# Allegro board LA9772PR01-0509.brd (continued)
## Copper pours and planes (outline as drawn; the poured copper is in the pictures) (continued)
+PCH_VCCCLK on BOTTOM (solid shape): 34.45,120.56 34.45,117.64 34.39,117.49 34.35,117.33 34.37,117.1 34.44,116.89 34.45,116.88 34.45,116.75 34.95,116.25 34.95,115.09 34.74,114.88 33.9,114.88 33.82,114.97 33.82,115.48 33.05,116.24 33.05,119.29 33.69,119.92 33.69,120.1 33.71,120.13 33.71,120.58 33.94,120.81 33.99,120.81 34.2,120.81
+PCH_VCCCLK on BOTTOM (solid shape): 35.34,104.18 35.34,102.14 35.21,102.02 34.96,102.02 34.83,101.89 34.83,101.26 34.71,101.13 34.2,101.13 33.94,101.38 33.94,101.89 33.95,102.53 33.44,102.14 33.42,102.05 33.34,102.02 33.05,102.02 32.82,102.25 32.8,102.33 32.8,103.16 33.05,103.41 33.31,103.41 33.56,103.67 33.56,104.3 33.69,104.43 34.32,104.43 34.45,104.56 34.96,104.56
+PCH_VCCCLK on IN2 (solid shape): outline of 1015 points within 30.64,101.89 36.36,119.16
+PCH_VCCCLK3_3 on TOP (solid shape): 28.65,102.2 28.95,102.05 29.25,102.2 29.33,102.16 29.44,102.08 29.57,102.06 29.79,102.06 29.88,101.97 29.88,101.8 29.88,101.76 29.88,101.03 29.88,100.99 29.88,100.95 29.88,100.49 29.63,100.24 28.86,100.24 28.61,100.49 28.61,100.5 28.61,101.24 28.61,101.25 28.6,101.48 28.42,101.63 28.4,101.63 28.36,101.68 28.36,102.02 28.4,102.06 28.41,102.06 28.5,102.1 28.57,102.16
+PCH_VCCCLK3_3 on BOTTOM (solid shape): 17.99,107.43 17.99,106.84 18.47,106.36 18.73,106.36 19.62,105.47 19.69,105.47 19.72,105.45 19.72,104.68 19.47,104.43 19.21,104.43 18.96,104.68 18.45,104.68 18.2,104.94 18.2,105.32 17.94,105.57 17.43,105.57 17.15,105.86 17.15,107.6 17.19,107.63 17.79,107.63
+PCH_VCCCLK3_3 on IN3 (solid shape): outline of 752 points within 18.7,100.24 31.4,105.95
+PWR_SRC on TOP (solid shape): 34.58,68.96 34.58,65.95 34.46,65.83 30.77,65.83 30.51,66.08 30.51,68.95 30.9,69.33 34.21,69.33
+PWR_SRC on TOP (solid shape): 160.31,99.35 160.31,93.51 160.05,93.25 155.86,93.25 155.61,93.51 155.61,100.49 155.86,100.75 158.91,100.75
+PWR_SRC on TOP (solid shape): 184.44,64.43 184.44,61.89 184.18,61.63 175.8,61.63 175.55,61.89 175.55,64.43 175.8,64.68 184.18,64.68
+PWR_SRC on BOTTOM (solid shape): 16.98,141.05 16.98,138.94 16.86,138.82 15.29,138.82 15.16,138.95 15.16,140.96 15.3,141.1 16.94,141.1
+PWR_SRC on BOTTOM (solid shape): 184.44,24.42 184.44,21.88 184.18,21.63 178.22,21.63 177.96,21.88 177.96,24.42 178.22,24.67 184.18,24.67
+PWR_SRC on BOTTOM (solid shape): 249.34,42.84 249.34,39.03 249.08,38.77 244.64,38.77 244.38,39.03 244.38,42.84 244.64,43.09 249.08,43.09
+PWR_SRC on BOTTOM (solid shape): 158.75,102.12 158.75,101.45 158.69,100.3 158.69,99.03 158.43,98.78 155.89,98.78 155.51,99.16 155.51,101.89 155.95,102.32 158.55,102.32
+PWR_SRC on BOTTOM (solid shape): 56.38,158.58 56.38,155.39 56.09,155.1 54.87,155.1 54.71,155.27 54.71,156.69 53.95,157.45 53.95,159.25 54.09,159.39 55.57,159.39
+PWR_SRC on BOTTOM (solid shape): 80.55,9.94 80.55,4.86 80.3,4.61 75.9,4.61 75.81,4.61 74.58,4.61 74.33,4.86 74.33,6.26 78.14,10.07 80.43,10.07
+PWR_SRC on BOTTOM (solid shape): 226.6,53.12 226.6,49.69 226.48,49.57 222.67,49.57 222.28,49.19 222.28,46.39 222.03,46.14 218.47,46.14 218.22,46.39 218.22,51.64 218.69,52.11 221.27,52.11 222.54,53.38 226.35,53.38
+PWR_SRC on BOTTOM (solid shape): 190.53,43.47 190.53,40.29 190.31,40.06 186.2,40.06 185.91,39.78 185.91,38.17 185.66,37.91 182.35,37.91 181.96,37.52 181.96,33.78 181.48,33.31 176.56,33.31 176.31,33.56 176.31,39.03 176.69,39.41 179.61,39.41 183.93,43.72 190.28,43.72
+PWR_SRC on BOTTOM (solid shape): 36.24,68.56 36.24,65.95 36.15,65.85 30.36,65.85 30.26,65.95 30.26,67.87 30.6,68.21 31.61,68.21 32.02,68.62 32.02,69.19 32.04,69.21 33.55,69.21 33.77,69.43 33.77,69.75 33.53,69.99 32.08,69.99 32.03,70.03 32.03,70.64 32.18,70.79 34.02,70.79
+PWR_SRC on BOTTOM (solid shape): 176.39,64.12 176.39,63.59 176.41,63.56 177.12,63.56 177.17,63.61 177.17,64.09 177.2,64.12 177.55,64.12 177.61,64.07 177.61,63.61 177.63,63.59 178.34,63.59 178.37,63.61 178.37,64.12 178.39,64.15 179.03,64.15 179.31,63.87 179.31,62.32 179.15,62.16 175.65,62.16 175.42,62.39 175.42,63.79 175.78,64.15 176.36,64.15
+PWR_SRC on BOTTOM (solid shape): outline of 81 points within 173.11,135.64 176.69,140.9
+PWR_SRC on IN1 (solid shape): 149.89,174.28 149.89,172.25 149.64,171.99 144.31,171.99 144.05,172.25 144.05,174.28 144.31,174.53 149.64,174.53
+PWR_SRC on IN1 (solid shape): 177.83,141.39 177.83,138.85 177.1,138.11 175.45,138.11 174.71,138.86 174.71,140.11 175.71,141.12 176.3,141.12 176.82,141.64 177.58,141.64
+PWR_SRC on IN2 (solid shape): 35.09,68.24 35.09,65.87 35.03,65.81 29.3,65.81 28.99,66.12 28.99,68.11 29.37,68.49 34.83,68.49
+PWR_SRC on IN2 (solid shape): 184.57,24.42 184.57,20.86 184.31,20.61 178.22,20.61 177.96,20.86 177.96,24.42 178.22,24.67 184.31,24.67
+PWR_SRC on IN2 (solid shape): 80.55,11.09 80.55,4.86 80.3,4.61 74.58,4.61 74.33,4.86 74.33,6.26 77.38,9.31 77.38,11.09 77.63,11.34 80.3,11.34
+PWR_SRC on IN3 (solid shape): 149.89,174.28 149.89,172.25 149.64,171.99 144.31,171.99 144.05,172.25 144.05,174.28 144.31,174.53 149.64,174.53
+PWR_SRC on IN3 (solid shape): 35.09,68.52 35.09,65.98 34.95,65.85 29.34,65.85 28.99,66.2 28.99,68.54 29.25,68.8 34.81,68.8
+PWR_SRC on IN3 (solid shape): 177.83,141.39 177.83,138.85 177.15,138.17 175.26,138.17 174.67,138.75 174.67,140.59 175.17,141.09 176.27,141.09 176.82,141.64 177.58,141.64
+PWR_SRC on IN3 (solid shape): 80.55,11.09 80.55,4.86 80.3,4.61 74.58,4.61 74.33,4.86 74.33,6.26 77.38,9.31 77.38,11.09 77.63,11.34 80.3,11.34
+PWR_SRC on IN3 (solid shape): 187.36,43.34 187.36,38.37 187.16,38.03 187.36,37.69 187.36,31.91 187.11,31.66 176.44,31.66 176.18,31.91 176.18,40.3 176.44,40.55 179.61,40.55 179.87,40.8 179.87,43.34 180.12,43.6 187.11,43.6
+PWR_SRC on IN4 (solid shape): 149.89,174.28 149.89,172.25 149.64,171.99 144.05,171.99 144.05,174.53 149.64,174.53
+PWR_SRC on IN4 (solid shape): 16.35,140.75 16.35,139 16.17,138.82 14.8,138.82 14.33,139.29 14.33,140.79 14.6,141.06 16.04,141.06
+PWR_SRC on IN4 (solid shape): 55.15,162.6 55.15,157.64 54.9,157.39 52.61,157.39 52.36,157.64 52.36,162.6 52.61,162.85 54.9,162.85
+PWR_SRC on IN4 (solid shape): outline of 2302 points within 174.41,23.53 249.97,64.43
+PWR_SRC_MXM on TOP (solid shape): 149.94,108.06 149.94,107.4 150.08,107.26 152.25,107.26 152.41,107.1 154.09,107.1 156.88,104.3 156.88,101.38 156.63,101.13 147.23,101.13 146.97,101.38 146.97,107.61 147.35,107.99 149.01,107.99 149.13,108.11 149.89,108.11
+SDC_IN on BOTTOM (solid shape): 29.52,74.81 30.97,74.81 31.51,74.26 31.51,73.56 32.01,73.06 32.01,72.11 32.11,72.01 32.11,70.98 32.04,70.9 31.18,70.9 30.98,70.69 30.98,70.03 30.93,69.99 29.47,69.99 29.24,69.75 29.24,69.44 29.47,69.21 30.97,69.21 30.99,69.19 30.99,68.46 30.86,68.34 29.73,68.34 29.5,68.11 26.58,68.11 26.32,68.36 26.32,71.03 24.8,72.55 24.8,74.97 25.05,75.22 29.11,75.22
+VCHGR on BOTTOM (solid shape): 211.13,46.38 211.13,44.89 211.35,44.68 211.69,44.68 211.91,44.89 211.91,46.37 211.95,46.4 212.9,46.4 213.17,46.14 213.17,43.86 213.31,43.72 217.2,43.72 217.59,43.34 217.59,39.43 216.24,38.09 212.61,38.09 212.43,38.26 212.43,39.13 211.9,39.66 209.09,39.66 208.85,39.9 208.85,40.46 208.5,40.8 206.74,40.8 206.61,40.93 206.61,44.38 206.82,44.59 210.23,44.59 210.42,44.78 210.42,46.34 210.5,46.42 211.1,46.42
+VDISPLAY_VCC on BOTTOM (solid shape): outline of 149 points within 21.13,161.96 24.29,170.49
BOOT1 on TOP (solid shape): 54.47,31.02 54.47,30.41 54.64,30.24 54.64,29.25 54.05,28.65 54.05,28.62 54.02,28.6 54.02,28.24 54.03,28.18 54.05,28.12 54.05,27.84 54,27.79 53.87,27.79 53.82,27.84 53.82,28.7 54.24,29.12 54.24,30.16 54.03,30.36 53.58,30.36 53.5,30.44 53.5,31.02 53.63,31.15 54.34,31.15
BOOT2 on TOP (solid shape): 48.88,28.13 48.88,27.9 49.87,26.91 51.32,26.91 51.34,26.88 51.34,26.73 51.31,26.7 50.94,26.7 50.89,26.7 50.01,26.7 50,26.71 49.86,26.73 49.72,26.69 49.71,26.68 49.36,26.68 48.8,27.24 48.17,27.24 48.12,27.29 48.12,28.13 48.19,28.2 48.8,28.2
BOOT3 on BOTTOM (solid shape): 40.12,74.13 40.12,72.86 40.06,72.81 39.89,72.81 39.84,72.86 39.84,73.77 39.66,73.95 38.64,73.95 38.39,73.7 38.39,73.19 38.26,73.06 37.75,73.06 37.63,73.19 37.63,74.33 37.88,74.59 39.66,74.59
BST1_3V on BOTTOM (solid shape): 252.64,59.35 252.64,57.19 252.38,56.93 251.88,56.93 251.62,57.19 251.62,59.35 251.88,59.6 252.38,59.6
BST1_5V on BOTTOM (solid shape): 242.6,59.85 242.6,57.57 242.35,57.31 241.21,57.31 240.95,57.57 240.95,59.85 241.21,60.11 242.35,60.11
BST_3V on BOTTOM (solid shape): 250.3,58.2 251.11,58.2 251.37,57.94 251.37,57.32 251.11,57.06 250.04,57.06 249.88,57.22 249.88,57.92 248.87,58.94 248.55,58.94 248.54,58.95 247.75,58.95 247.68,59.02 247.68,59.16 247.71,59.19 249.31,59.19
BST_5V on BOTTOM (solid shape): 245.5,59.13 245.5,59 245.44,58.94 244.35,58.94 243.87,58.47 243.87,58.47 243.87,57.83 243.81,57.77 243.2,57.77 243.11,57.86 243.11,58.66 243.26,58.8 243.85,58.8 244.24,59.19 245.44,59.19
BST_+1.05VSP on BOTTOM (solid shape): 20.61,144.56 20.61,143.93 20.48,143.8 20.35,143.8 20.23,143.93 19.85,143.93 19.72,143.8 18.32,143.8 18.2,143.93 18.2,144.56 18.27,144.64 20.53,144.64
CHG on BOTTOM (solid shape): 212.38,51.09 212.38,47.47 212.35,47.45 211.92,47.45 211.91,47.46 211.91,48.98 211.68,49.21 211.37,49.21 211.15,48.98 211.15,47.46 211.13,47.45 210.36,47.45 209.46,46.54 202.78,46.54 202.47,46.85 202.47,54.01 202.73,54.27 209.2,54.27
CPU_B+ on TOP (solid shape): 45.12,48.3 45.12,42.33 44.99,42.2 43.6,42.2 43.34,42.45 43.34,48.3 43.6,48.55 44.87,48.55
CPU_B+ on BOTTOM (solid shape): outline of 208 points within 39.53,43.85 45.12,76.24
CPU_B+ on TOP: 32.08,77.15 32.94,78.01 37.63,78.01 37.86,77.78 37.85,77.73 37.85,76.85 37.86,76.78 37.88,76.69 37.88,76.36 37.92,76.32 37.95,76.25 37.91,76.17 37.78,75.81 38.03,75.52 38.42,75.6 38.53,75.98 38.55,76.07 38.63,76.11 38.9,76.11 38.9,76.11 39.05,76.08 39.19,76.11 39.2,76.11 42.07,76.11 42.33,75.86 42.33,74.46 42.71,74.08 43.34,74.08 43.6,73.82 43.6,72.17 43.34,71.92 42.37,71.92 42.25,71.93 42.13,71.92 41.44,71.92 40.55,71.03 40.55,70.38 40.54,70.37 40.52,70.24 40.54,70.12 40.55,70.11 40.55,69.25 41.18,68.62 41.18,64.55 43.47,62.27 43.47,57.19 43.21,56.93 42.58,56.93 42.45,57.06 36.74,57.06 36.48,57.31 36.48,67.98 33.66,70.8 30.29,70.8 28.36,68.87 25.82,68.87 25.56,69.12 25.56,77.51 25.82,77.76 28.75,77.76 29.36,77.15
DH_1.35V on BOTTOM (solid shape): 189.14,63.28 189.14,62.9 188.88,62.65 186.34,62.65 186.09,62.9 186.09,63.28 186.34,63.54 188.88,63.54
DH_1.35V on BOTTOM (solid shape): 178.39,75.94 178.39,74.92 178.6,74.71 179.1,74.71 179.36,74.46 179.36,74.33 179.1,74.08 178.66,74.08 178.53,74.08 178.09,74.08 177.96,74.2 177.96,74.46 178.19,74.69 178.19,75.95 178.24,76 178.33,76
DL_1.35V on BOTTOM (solid shape): 179.89,76.33 179.89,76.21 180.37,75.73 180.37,75.47 180.12,75.22 179.74,75.22 179.61,75.22 178.98,75.86 178.98,76.24 178.98,76.35 179.03,76.4 179.82,76.4
DL_CHG on BOTTOM (solid shape): 187.23,52.61 187.23,51.98 187.11,51.85 185.58,51.85 185.45,51.98 185.45,52.61 185.58,52.74 187.11,52.74
LG_3V on BOTTOM (solid shape): 248.67,57.35 248.67,57.03 248.61,56.97 247.85,56.97 247.28,57.54 247.28,58.28 247.35,58.34 247.68,58.34
LG_3V on BOTTOM (solid shape): 248.83,54.9 248.83,53.77 248.94,53.67 249.8,53.67 250.1,53.38 250.1,52.74 249.84,52.49 248.19,52.49 248.07,52.61 248.07,54.9 248.11,54.94 248.79,54.94
LG_5V on BOTTOM (solid shape): 244.76,50.91 244.76,50.2 244.51,49.95 243.11,49.95 242.99,50.07 242.99,50.84 243.11,50.96 244.31,50.96 244.36,51.01 244.66,51.01
LG_5V on BOTTOM (solid shape): 245.88,58.29 245.88,58.08 245.87,58.02 245.87,57.53 245.63,57.29 245.63,57.16 245.18,56.71 244.67,56.71 244.55,56.84 244.55,57.1 245.18,57.73 245.44,57.73 245.69,57.98 245.69,58.3 245.75,58.35 245.82,58.35
LG_5V on IN1 (solid shape): 244.76,50.91 244.76,50.2 244.51,49.95 243.6,49.95 242.93,50.61 242.93,50.84 243.11,51.01 244.66,51.01
LG_5V on IN1 (solid shape): 245.65,57.69 245.65,57.34 244.33,56.01 244.24,56.01 243.8,56.45 243.8,56.61 244.98,57.78 245.14,57.78 245.31,57.95 245.4,57.95
LG_+1.05VSP on BOTTOM (solid shape): 25.91,139.06 25.91,137.06 25.72,136.87 25.37,136.87 25.26,136.98 25.26,139.11 25.34,139.19 25.78,139.19
LG_+1.05VSP on BOTTOM (solid shape): 23.53,144.44 23.53,143.29 23.4,143.17 23.02,143.17 22.89,143.29 22.89,143.55 22.64,143.8 22.41,143.8 22.34,143.88 22.34,144.56 22.41,144.64 23.33,144.64
LG_+1.05VSP on IN1 (solid shape): 25.76,139.02 25.76,138.19 25.59,138.01 24.8,138.01 24.26,138.55 24.26,138.69 24.74,139.17 25.61,139.17
LGATE1 on TOP (solid shape): 48.93,54.9 48.93,53.88 48.17,53.12 47.79,53.12 47.66,53.25 47.66,53.88 47.91,54.14 47.91,54.9 48.17,55.15 48.68,55.15
LGATE1 on TOP (solid shape): 52.21,30.26 52.76,29.7 52.76,29.45 52.74,29.42 52.74,29.07 52.84,28.97 52.84,27.82 52.79,27.77 52.66,27.77 52.61,27.82 52.61,28.12 52.63,28.18 52.63,28.24 52.63,28.89 52.36,29.17 52.36,29.37 51.8,29.93 51.8,30.14 51.93,30.26 52.17,30.26
LGATE1 on IN4 (solid shape): 48.8,54.27 48.8,53.63 48.42,53.25 48.42,51.85 47.41,51.85 47.41,53.5 48.29,54.39 48.68,54.39
LGATE1 on IN4 (solid shape): 52.61,31.02 52.61,29.86 52.79,29.68 52.79,29.45 52.64,29.3 52.43,29.3 51.6,30.14 51.6,31.02 51.8,31.23 52.41,31.23
LGATE2 on TOP (solid shape): 50.52,29.51 50.52,29.31 51.14,28.69 51.32,28.69 51.33,28.68 51.44,28.66 51.56,28.67 51.58,28.68 51.62,28.64 51.62,27.82 51.57,27.77 51.49,27.77 51.04,28.23 50.86,28.23 50.2,28.89 50.12,28.89 49.56,29.45 49.56,29.53 50,29.96 50.07,29.96
LGATE3 on TOP (solid shape): 48.93,69.85 48.93,68.01 48.82,67.9 48.08,67.9 47.98,68 47.98,69.89 48.11,70.01 48.77,70.01
LGATE3 on BOTTOM (solid shape): 41.74,71.51 41.74,70.67 41.59,70.52 41.33,70.52 41.16,70.7 40.9,70.7 40.83,70.78 40.83,71.56 40.9,71.64 41.61,71.64
LGATE3 on IN1 (solid shape): 41.69,71.54 41.69,71.16 42.45,70.39 42.45,70.14 42.33,70.01 41.82,70.01 41.06,70.78 41.06,71.54 41.18,71.66 41.56,71.66
LX_CHG on BOTTOM (solid shape): 202.09,55.15 202.09,45.38 201.84,45.12 196.63,45.12 196.38,45.38 196.38,50.59 196.39,50.71 196.38,50.83 196.38,51.22 195.87,51.73 194.73,51.73 194.47,51.47 194.47,50.2 194.22,49.95 191.04,49.95 190.15,49.06 187.99,49.06 187.74,49.31 187.74,52.87 187.99,53.12 190.66,53.12 190.92,53.38 190.92,55.28 191.17,55.54 201.71,55.54
P1_SW on TOP (solid shape): 51.85,57.95 51.85,57.44 52.36,56.93 53.12,56.93 53.37,57.19 53.37,57.69 53.5,57.82 54.14,57.82 54.26,57.69 54.26,54.39 54.01,54.14 51.22,54.14 50.96,54.39 50.96,55.41 50.71,55.66 48.17,55.66 47.91,55.92 47.91,60.36 48.17,60.62 49.18,60.62
P2_SW on TOP (solid shape): 52.23,46.65 53.25,46.65 53.37,46.77 55.28,46.77 55.66,46.39 55.66,41.18 55.41,40.93 49.64,40.93 49.5,41.07 49.5,46.33 49.95,46.77 52.1,46.77
P3_SW on TOP (solid shape): 50.33,75.47 50.33,74.53 50.91,73.95 54.37,73.95 54.39,73.95 54.77,73.57 54.77,70.77 54.26,70.27 53.63,70.27 53.37,70.52 53.37,70.9 53.25,71.03 52.23,71.03 52.1,70.9 52.1,70.65 51.98,70.52 48.29,70.52 48.04,70.78 48.04,73.82 48.17,73.95 49.74,73.95 49.74,73.9 49.75,73.85 49.77,73.79 49.79,73.75 49.82,73.7 49.85,73.66 49.9,73.63 49.94,73.6 49.99,73.58 50.04,73.57 50.1,73.57 50.15,73.57 50.2,73.58 50.25,73.6 50.3,73.63 50.34,73.66 50.38,73.7 50.41,73.75 50.43,73.79 50.45,73.85 50.45,73.9 50.45,73.95 50.45,74 50.43,74.05 50.41,74.1 50.38,74.15 50.34,74.19 50.3,74.22 50.25,74.25 50.2,74.27 50.15,74.28 50.1,74.28 50.04,74.28 49.99,74.27 49.94,74.25 49.9,74.22 49.85,74.19 49.82,74.15 49.79,74.1 49.77,74.05 49.75,74 49.74,73.95 48.17,73.95 48.29,74.08 48.93,74.08 49.44,74.59 49.44,75.47 49.56,75.6 50.2,75.6
PBATT+ on BOTTOM (solid shape): 201.2,38.67 201.2,35.24 200.54,34.58 193.71,34.58 193.46,34.83 193.46,38.26 193.58,38.39 195.49,38.39 195.74,38.14 195.74,37.5 196.2,37.04 197.01,37.04 197.42,37.45 197.42,39 197.51,39.09 200.78,39.09
PBATT+_C on TOP (solid shape): outline of 1229 points within 158.53,15.72 204.12,36.74
PBATT+_C on BOTTOM (solid shape): 204.25,32.55 204.25,29.77 204.12,29.64 196.6,29.64 196.43,29.82 196.43,31.49 196.8,31.86 196.8,32.59 197.07,32.87 203.93,32.87
PBATT+_C on IN4 (solid shape): outline of 291 points within 158.53,15.78 204.25,27.72
PBATT_IN_SS on BOTTOM (solid shape): 193.07,37.5 193.07,33.69 192.82,33.44 189.01,33.44 186.85,31.28 185.45,31.28 185.33,31.15 185.33,30.26 185.2,30.14 184.44,30.14 184.18,29.88 184.18,29.12 183.93,28.87 180.25,28.87 179.99,29.12 179.99,30.58 179.6,30.97 177.95,30.97 177.83,31.09 177.83,32.68 177.96,32.8 182.15,32.8 182.53,33.18 182.53,37.03 182.88,37.37 187.62,37.37 188.07,37.82 192.75,37.82
PHASE1 on TOP (solid shape): 43.6,54.9 43.6,54.27 44.74,53.12 44.74,52.49 44.48,52.23 43.98,52.23 42.58,53.63 42.58,54.9 42.83,55.15 43.34,55.15
PHASE1 on TOP (solid shape): 53.2,31.02 53.2,30.29 53.4,30.08 53.4,29.04 53.23,28.88 53.23,27.84 53.18,27.79 53.06,27.79 53.02,27.82 53.02,28.99 52.87,29.14 52.87,29.35 52.94,29.42 52.94,29.73 52.87,29.8 52.87,29.98 52.49,30.36 52.31,30.36 52.28,30.39 52.28,31.02 52.31,31.05 53.17,31.05
PHASE1 on IN3 (solid shape): 45.88,52.23 45.88,51.22 44.99,51.22 43.98,52.23 43.98,53.5 44.1,53.63 44.48,53.63
PHASE1 on IN3 (solid shape): 53.78,31.13 53.78,30.64 53.4,30.26 53.4,29.12 53.27,28.99 53.02,28.99 52.87,29.14 52.87,29.35 52.94,29.42 52.94,29.73 52.87,29.8 52.87,30.9 53.12,31.15 53.76,31.15
PHASE2 on TOP (solid shape): 45.12,40.17 45.12,38.39 44.87,38.14 44.36,38.14 44.1,38.39 44.1,40.11 44.1,40.17 44.36,40.42 44.87,40.42
PHASE2 on TOP (solid shape): 50.96,27.72 51.29,27.72 51.37,27.65 51.37,27.54 51.32,27.49 50.48,27.49 49.49,28.48 48.17,28.48 48.04,28.61 48.04,29.5 48.17,29.63 49.06,29.63
PHASE2 on IN4 (solid shape): 49.84,29.09 49.84,28.84 50.43,28.26 50.43,28.03 50.33,27.93 50.05,27.93 49.49,28.48 49.28,28.48 48.66,29.11 48.66,29.49 48.8,29.63 49.31,29.63
PHASE3 on BOTTOM (solid shape): 38.39,72.5 38.39,71.92 38.52,71.79 39.05,71.79 39.2,71.64 39.53,71.64 39.61,71.56 39.61,70.72 39.53,70.65 38.39,70.65 37.63,71.41 37.63,72.43 37.75,72.55 38.34,72.55
PHASE3 on IN4 (solid shape): 39.28,71.66 39.28,70.9 39.79,70.39 39.79,70.14 39.4,69.76 39.28,69.76 38.52,70.52 38.52,71.66 38.64,71.79 39.15,71.79
PWR_SRC_ON on BOTTOM (solid shape): 53.62,159.24 53.62,155.46 53.21,155.05 52.41,155.05 52.14,155.32 52.14,155.72 52.36,155.95 52.36,157.19 52.1,157.46 51.47,157.46 51.37,157.56 51.37,157.95 51.45,158.03 52.03,158.03 52.44,158.44 52.44,159.08 52.7,159.35 53.51,159.35
SNB_CPU_P1 on TOP (solid shape): 49.06,63.92 49.06,61.25 48.8,61 48.17,61 47.91,61.25 47.91,63.92 48.17,64.17 48.8,64.17
SNB_CPU_P3 on TOP (solid shape): 48.93,75.73 48.93,74.71 48.8,74.59 46.9,74.59 46.77,74.71 46.77,76.24 46.9,76.36 48.29,76.36
SNUB_1.5VSP on BOTTOM (solid shape): 258.53,27.98 258.73,27.98 258.99,27.72 258.99,27.09 258.73,26.83 256.57,26.83 256.32,27.09 256.32,27.72 256.57,27.98 258.51,27.98
SNUB_1.35V on BOTTOM (solid shape): 188.38,74.97 189.14,74.97 189.39,74.71 189.39,73.7 189.14,73.44 186.72,73.44 186.47,73.7 186.47,75.35 186.72,75.6 187.74,75.6
SW1 on BOTTOM (solid shape): 244.34,60.09 244.34,59.7 244.46,59.59 245.4,59.59 245.44,59.55 245.44,59.38 245.41,59.36 244.16,59.36 243.92,59.13 243.18,59.13 242.79,59.51 242.79,60.47 242.99,60.68 243.76,60.68
SW1 on BOTTOM (solid shape): 242.48,55.28 242.48,53.12 242.6,53 242.6,49.82 242.35,49.57 242.35,48.55 242.1,48.3 240.57,48.3 240.19,47.92 240.19,45.38 239.94,45.12 236.13,45.12 235.87,45.38 235.87,50.58 239.94,54.65 239.94,55.41 240.06,55.54 242.22,55.54
SW1 on IN1 (solid shape): 239.69,52.65 239.69,50.69 239.55,50.55 239.14,50.55 238.92,50.77 238.92,52.69 239,52.77 239.56,52.77
SW1 on IN1 (solid shape): 243.99,60.58 243.99,60.27 243.3,59.59 243.3,59.6 242.15,59.6 241.95,59.8 241.95,59.9 242.75,60.7 243.86,60.7
SW2 on BOTTOM (solid shape): 251.11,59.65 251.11,58.71 250.86,58.46 250.35,58.46 249.46,59.35 247.75,59.35 247.68,59.42 247.68,59.49 247.74,59.55 248.75,59.55 249.09,59.89 249.32,59.89 249.34,59.9 250.86,59.9
SW2 on BOTTOM (solid shape): 253.27,55.54 253.27,54.39 254.16,53.5 257.72,53.5 257.97,53.25 257.97,46.01 257.72,45.76 254.03,45.76 253.78,46.01 253.78,49.31 253.4,49.69 252.26,49.69 251.95,49.39 251.95,48.25 251.88,48.17 250.22,48.17 249.97,48.42 249.97,49.95 250.48,50.46 250.48,54.14 252.13,55.79 253.02,55.79
SW2 on IN1 (solid shape): 251.17,59.7 251.17,58.89 251.03,58.75 249.81,58.75 249.09,59.47 249.09,59.65 249.34,59.9 250.97,59.9
SW_1.35V on BOTTOM (solid shape): 185.2,76.11 185.2,72.93 185.45,72.68 190.79,72.68 191.04,72.43 191.04,64.04 190.79,63.79 186.47,63.79 186.22,64.04 186.22,68.11 185.96,68.36 182.91,68.36 182.66,68.62 182.66,76.11 182.91,76.36 184.95,76.36
SW_1.35V on BOTTOM (solid shape): 178.76,76 178.8,75.95 178.8,75.78 179.49,75.09 179.56,75.09 179.92,75.09 180.45,74.56 180.45,73.26 180.25,73.06 178.85,73.06 178.67,73.24 178.67,73.87 178.75,73.95 179.41,73.95 179.64,74.18 179.64,74.48 179.05,75.07 178.68,75.07 178.59,75.16 178.59,75.95 178.64,76
SW_+1.05VSP on TOP (solid shape): 18.83,138.09 18.83,135.34 18.84,135.33 18.84,133.83 19.01,133.66 20.31,133.66 20.65,133.31 20.65,132.17 20.18,131.7 17.34,131.7 13.88,135.16 13.88,137.07 14.13,137.32 15.91,137.32 16.8,138.21 18.7,138.21
SW_+1.05VSP on BOTTOM (solid shape): 21.62,144.56 21.62,143.55 22.39,142.78 22.39,142.15 22.13,141.9 21.12,141.9 20.94,142.07 20.94,143.01 21.32,143.39 21.32,144.56 21.42,144.66 21.52,144.66
SW_+1.05VSP on BOTTOM (solid shape): 25.46,136.3 25.57,136.3 25.69,136.17 25.69,131.54 25.19,131.03 18.01,131.03 17.08,131.97 17.08,134.18 17.44,134.54 18.18,134.54 19.04,133.68 20.16,133.68 20.31,133.83 20.31,134.92 20.51,135.13 21.89,135.13 23.06,136.3 25.46,136.3
SW_+1.05VSP on IN1 (solid shape): 21.46,133.23 21.46,132.81 20.77,132.12 20.1,132.12 19.92,132.31 19.92,132.75 19.96,132.79 19.96,133.29 20.09,133.42 21.27,133.42
SW_+1.05VSP on IN1 (solid shape): 22.26,142.91 22.26,141.9 21.5,141.13 21.24,141.13 20.99,141.39 20.99,141.9 21.62,142.53 21.62,142.91 21.75,143.04 22.13,143.04
UG_3V on BOTTOM (solid shape): 253.42,49.26 253.42,48.04 253.27,47.89 252.81,47.89 252.21,48.5 252.21,49.26 252.36,49.41 253.27,49.41
UG_3V on BOTTOM (solid shape): 249.37,58.24 249.37,57.98 249.31,57.92 248.4,57.92 248.36,57.95 248.3,57.97 247.7,58.58 247.7,58.7 247.75,58.75 248.86,58.75
UG_3V on IN4 (solid shape): 250.13,57.43 250.13,57.25 249.59,56.71 249.5,56.71 248.07,58.15 248.07,58.33 248.56,58.82 248.74,58.82
UG_5V on BOTTOM (solid shape): 243.67,49.52 243.67,48.6 243.49,48.42 242.73,48.42 242.6,48.55 242.6,49.44 242.86,49.69 243.49,49.69
UG_5V on BOTTOM (solid shape): 245.56,58.75 245.56,58.5 245.55,58.46 245.55,58.43 245.55,58.16 245.31,57.92 244.17,57.92 244.04,58.05 244.04,58.43 244.42,58.81 245.5,58.81
UG_5V on IN4 (solid shape): 245.18,58.44 245.18,57.98 245.06,57.86 243.28,57.86 243.15,57.98 243.15,58.75 243.28,58.87 244.75,58.87
UG_5V on IN4 (solid shape): 243.67,49.57 243.67,48.6 243.42,48.35 242.3,48.35 241.99,48.65 241.99,50.02 242.3,50.33 242.91,50.33
UG_+1.05VSP on BOTTOM (solid shape): 20.07,134.89 20.07,134.04 19.85,133.82 19.13,133.82 18.99,133.96 18.99,134.82 19.18,135.01 19.95,135.01
UG_+1.05VSP on BOTTOM (solid shape): 21.12,144.59 21.12,143.44 20.84,143.17 19.97,143.17 19.85,143.29 19.85,143.57 19.95,143.67 20.23,143.67 20.28,143.62 20.58,143.62 20.84,143.88 20.84,144.59 20.89,144.64 21.07,144.64
UG_+1.05VSP on IN1 (solid shape): 19.66,135.6 19.66,134.04 19.45,133.82 19.03,133.82 18.83,134.01 18.83,135.6 18.93,135.7 19.57,135.7
UG_+1.05VSP on IN1 (solid shape): 20.99,143.67 20.99,143.29 20.86,143.17 20.48,143.17 19.85,142.53 19.34,142.53 19.08,142.78 19.08,143.04 19.85,143.8 20.86,143.8
UGATE1 on TOP (solid shape): 54.03,30.01 54.03,29.12 53.64,28.73 53.64,27.84 53.59,27.79 53.46,27.79 53.41,27.84 53.41,28.83 53.53,28.94 53.53,30.03 53.65,30.16 53.88,30.16
UGATE1 on IN1 (solid shape): 54.9,31.02 54.9,29.98 53.91,28.99 53.63,28.99 53.53,29.09 53.53,30.03 54.14,30.64 54.14,31.02 54.24,31.13 54.8,31.13
UGATE2 on TOP (solid shape): 50.45,27.32 51.29,27.32 51.34,27.26 51.34,27.14 51.29,27.09 49.95,27.09 49.18,27.85 49.18,28.1 49.31,28.23 49.54,28.23
UGATE2 on TOP (solid shape): 45.12,41.57 45.12,41.06 44.87,40.8 44.23,40.8 43.98,40.55 43.98,40.17 43.72,39.91 43.21,39.91 42.96,40.17 42.96,41.57 43.21,41.82 44.87,41.82
UGATE2 on IN4 (solid shape): 49.18,28.23 49.54,28.23 50.2,27.57 50.2,27.34 50.07,27.21 49.06,27.21 48.17,28.1 48.17,28.61 48.29,28.74 48.68,28.74
UGATE3 on BOTTOM (solid shape): 39.61,73.65 39.61,72.86 39.56,72.81 39.23,72.81 39.15,72.73 39.15,72.4 39.02,72.27 38.74,72.27 38.64,72.38 38.64,73.59 38.77,73.72 39.53,73.72
UGATE3 on IN4 (solid shape): 40.12,73.42 40.12,72.91 40.01,72.81 39.53,72.81 39,72.27 38.67,72.27 38.52,72.43 38.52,73.32 38.77,73.57 39.96,73.57
VLDOIN_1.35V on BOTTOM (solid shape): 177.15,74.79 177.26,74.81 177.33,74.72 177.33,73.84 177.33,71.92 177.05,71.64 175.01,71.64 174.99,71.61 174.99,71.11 174.96,71.08 174.84,71.08 174.84,71.61 174.81,71.64 174.41,71.64 174.28,71.77 174.28,73.06 174.53,73.32 176.18,73.32 176.56,73.7 176.56,74.46 176.69,74.59 176.95,74.59
N16855849 on TOP (solid shape): 54.52,32.42 54.52,31.79 54.39,31.66 52.36,31.66 52.23,31.79 52.23,32.02 52.23,32.02 52.23,32.42 52.36,32.55 54.39,32.55
N17657331 on BOTTOM (solid shape): 217.71,44.99 217.73,44.99 218.35,44.99 218.47,44.87 218.47,44.11 218.73,43.85 220.25,43.85 220.38,43.72 220.38,42.71 220.63,42.45 222.28,42.45 222.54,42.2 222.54,38.52 222.28,38.26 220.38,38.26 220.13,38.52 220.13,39.66 219.87,39.91 218.22,39.91 217.97,40.17 217.97,43.47 217.46,43.98 215.81,43.98 215.68,44.11 215.68,44.87 215.81,44.99 216.87,44.99
N17657445 on BOTTOM (solid shape): 203.15,44.23 203.15,39.76 202.9,39.52 196.62,39.52 196.25,39.89 196.25,44.61 196.38,44.74 202.64,44.74
N19407600 on BOTTOM (solid shape): 160.16,106.79 160.16,104.65 159.91,104.4 158.81,104.4 157.83,105.38 157.83,106.96 157.86,106.98 159.97,106.98
N20156535 on BOTTOM (solid shape): 259.62,154.66 259.62,152.27 259.59,152.23 259.56,152.2 258.91,152.2 258.53,151.81 258.91,151.43 259.43,151.43 259.43,151.31 259.48,151.07 259.61,150.87 259.62,150.85 259.62,150.79 259.62,150.75 259.62,148.12 260.45,147.29 260.45,145.77 260.19,145.51 258.67,145.51 257.97,146.21 257.97,154.67 258.17,154.87 259.41,154.87
N48711348 on TOP (solid shape): 47.53,29.5 47.53,27.34 47.41,27.21 46.77,27.21 46.64,27.34 46.64,29.5 46.77,29.63 47.41,29.63
N51290432 on BOTTOM (solid shape): 37.12,74.08 37.12,71.66 36.99,71.54 36.36,71.54 36.23,71.66 36.23,74.08 36.36,74.2 36.99,74.2
N51302473 on BOTTOM (solid shape): 40.6,71.59 40.6,70.78 40.32,70.5 40.32,68.97 40.24,68.9 38.72,68.9 38.49,69.12 38.49,69.71 39.18,70.39 39.58,70.39 39.84,70.65 39.84,71.59 39.89,71.64 40.55,71.64
N85751870 on BOTTOM (solid shape): 19.39,142.99 20.28,142.99 20.35,142.91 20.35,142.15 20.23,142.02 18.7,142.02 18.2,142.53 18.2,143.17 18.32,143.29 19.08,143.29

Small or netless copper shapes (teardrops, artwork), in the pictures only: 203 on TOP, 13 on BOTTOM, 1 on IN1, 137 on IN2, 1 on IN3, 1 on IN4

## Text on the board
Ref Des/Silkscreen Bottom: PWBP/N: | Rev:X00 | ALL RIGHT RESERVED | COPYRIGHT 2014
User.Comments: LA9772P | 2014-05-08 | 2015-05-08 | Minjia | VAQ10 | 0.1(X00)
Ref Des/Silkscreen Top: 2 | H3 | 1 | 4 | H5 | H7 | M2x3 | 5 | H8 | 3
COMPVAL_TYPE_BOTTOM: 26.09 | 7.20 | 4.70 | 4.05 | 11.15 | 14.10 | 28.81 | 124.61 | 130.17 | 140.76 | 144.42 | 133.21 | 92.70 | 213.00 | 225.25 | 234.80 | 92.95 | 114.75 | 141.85 | 30.30 | 8.70 | 2.63 | 0.10 | 83.00 | 80.25 | 51.20 | 156.96 | 154.35 | 151.44 | 119.15 | 117.20 | 28.70 | 23.18 | 14.95 | 0.67 | 0.00 | 10.10 | 2.90 | 9.90 | 19.74 | 67.86 | 102.55 | 116.15 | 132.30 | 137.30 | 190.35 | 86.50
COMPVAL_TYPE_TOP: 139.00 | 114.20 | 105.50 | 56.00 | 0.00 | 25.65 | 0.60 | 46.80 | 79.30 | 100.99 | 135.50 | 26.65 | 102.55 | 116.15 | 124.75 | 121.94 | 121.04 | 199.16 | 217.25 | 47.50 | 8.70 | 2.10
USER_PART_NUM_BOTTOM: 161.20 | 0.00 | 236.40
DEVICE_TYPE_BOTTOM: 161.90 | 0.00 | 236.40
USER_PART_NUM_TOP: 27.20 | 10.20 | {\Fgdt;n}\Ftxt;6.00 | {\Fgdt;n}\Ftxt;2.80 | 8.68 | {\Fgdt;n}\Ftxt;4.20 | 17.57 | 17.80 | {\Fgdt;n}\Ftxt;3.80 | {\Fgdt;n}\Ftxt;7.00 | 38.46 | {\Fgdt;n}\Ftxt;8.00 | 92.57 | 123.60 | {\Fgdt;n}\Ftxt;5.00 | 149.80 | 149.13 | 109.13 | 88.20 | 224.80 | 225.80 | 230.30 | 2.00 | 2.10 | 154.40 | 83.50 | 72.27 | 10.54 | 0.40 | 146.00 | 142.00 | 72.00 | 67.00 | 3.00 | 3.20 | 15.00 | 6.50 | 4.00 | 0.00 | {\Fgdt;n}\Ftxt;3.20 | {\Fgdt;n}\Ftxt;3.30 | {\Fgdt;n}\Ftxt;2.30 | 35.31 | 58.93 | 63.30 | 62.43 | 0.10 | 114.80 | {\Fgdt;n}\Ftxt;4.10 | 152.35 | {\Fgdt;n}\Ftxt;5.50 | 223.80 | 228.95
DEVICE_TYPE_TOP: 54.60 | 48.00 | 0.00 | 8.50 | {\Fgdt;n}\Ftxt;8.00 | {\Fgdt;n}\Ftxt;7.00 | {\Fgdt;n}\Ftxt;4.20 | {\Fgdt;n}\Ftxt;2.90 | {\Fgdt;n}\Ftxt;5.50 | 34.00 | 27.60
PAGE_OUTLINE: 236.40 | 161.90 | 39.15 | 0.00 | 16.80
User.10: 26.09 | 7.20 | 4.05 | 11.15 | 14.10 | 28.81 | 124.61 | 130.17 | 140.76 | 144.42 | 133.21 | 92.70 | 213.00 | 225.25 | 234.80 | 92.95 | 114.75 | 141.85 | 30.30 | 8.70 | 2.63 | 0.10 | 83.00 | 80.25 | 51.20 | 156.96 | 154.35 | 151.44 | 119.15 | 28.70 | 23.18 | 14.95 | 0.67 | 0.00 | 10.10 | 2.90 | 9.90 | 19.74 | 67.86 | 102.55 | 116.15 | 132.30 | 137.30 | 190.35 | 86.50
User.11: 139.00 | 114.20 | 105.50 | 56.00 | 0.00 | 25.65 | 0.60 | 46.80 | 79.30 | 100.99 | 135.50 | 26.65 | 102.55 | 116.15 | 124.75 | 121.94 | 121.04 | 199.16 | 217.25 | 47.50 | 8.70 | 2.10
User.12: 161.20 | 0.00 | 236.40
User.13: 161.90 | 0.00 | 236.40
User.14: 27.20 | 10.20 | {\Fgdt;n}\Ftxt;6.00 | {\Fgdt;n}\Ftxt;2.80 | 8.68 | {\Fgdt;n}\Ftxt;4.20 | 17.57 | 17.80 | {\Fgdt;n}\Ftxt;3.80 | {\Fgdt;n}\Ftxt;7.00 | 38.46 | {\Fgdt;n}\Ftxt;8.00 | 92.57 | 123.60 | {\Fgdt;n}\Ftxt;5.00 | 149.80 | 149.13 | 109.13 | 88.20 | 224.80 | 225.80 | 230.30 | 2.00 | 2.10 | 154.40 | 83.50 | 72.27 | 10.54 | 0.40 | 146.00 | 142.00 | 72.00 | 67.00 | 3.00 | 3.20 | 15.00 | 6.50 | 4.00 | 0.00 | {\Fgdt;n}\Ftxt;3.20 | {\Fgdt;n}\Ftxt;3.30 | {\Fgdt;n}\Ftxt;2.30 | 35.31 | 58.93 | 63.30 | 62.43 | 0.10 | 114.80 | {\Fgdt;n}\Ftxt;4.10 | 152.35 | {\Fgdt;n}\Ftxt;5.50 | 223.80 | 228.95
User.15: 54.60 | 48.00 | 0.00 | 8.50 | {\Fgdt;n}\Ftxt;8.00 | {\Fgdt;n}\Ftxt;7.00 | {\Fgdt;n}\Ftxt;4.20 | {\Fgdt;n}\Ftxt;2.90 | {\Fgdt;n}\Ftxt;5.50 | 34.00 | 27.60
User.16: 236.40 | 161.90 | 39.15 | 0.00 | 16.80
User.36: trace Width | Width/space | 8.2mil | 7mil | 6mil | 5mil | 5.5mil | 5.8mil | 5 / 3.5 | 4.3mil | 4mil | 5.8 / 4.2 | 5.5 / 4.7 | 4 / 4.9 | 5.5 / 4.5 | 5.3 / 4.7 | 4.6 / 4.7 | 4 / 4.5 | 5 / 4.8 | 4.3 / 4.7 | 4 / 5 | 4.6 / 6.6 | 4 / 6.5 | 5 / 7 | 3.5 / 10 | 4 / 10 | 7/5.5 | 9/4.5 | SB_1_45mm-10L(4mil & 5mil 50ohm)_WithoutC_121008.pdf | L1-TOP | L2-GND1 | L3-IN1 | L4-VCC | L5-IN2 | L6-IN3 | L7-GND2 | L8-IN4 | L9-GND3 | L10-BOT | LAYER | NAME | STACKUP: 10 LAYER | 35 ohm | 39 ohm | 43 ohm | THICKNESS=1.45mm | 75 ohm | 50 ohm | 88 ohm | 80 ohm | L5/L7 | Ref | 85 ohm | 90 ohm | 100 ohm | no ref
User.37: FIGURE | SIZE | 8.0 | 9.0 | 10.0 | 20.0 | 22.0 | 24.0 | 30.0 | 31.0 | 35.0 | 36.0 | 39.0 | 55.0 | 91.0 | 110.0 | 126.0 | 130.0 | 150.0 | 161.0 | 40.0 | 43.0 | 63.0 | 65.0 | 67.0 | 39.0x33.0 | 45.0x37.0 | 55.0x31.0 | 59.0x31.0 | 63.0x24.0 | 67.0x20.0 | 75.0x24.0 | 75.0x37.0 | 83.0x39.0 | 94.0x24.0 | 94.0x31.0 | 94.0x39.0 | 102.0x31.0 | 112.0x39.0 | 118.0x33.0 | 120.0x39.0 | 67.0x43.0 | 161.0x83.0 | 244.0x126.0 | DRILL CHART: TOP to BOTTOM | ALL UNITS ARE IN MILS | PLATED | NON-PLATED | QTY | 5220 | 9 | 1438 | 20 | 19 | 15 | 7 | 18 | 8 | 4 | 16 | 2 | 1 | 3
